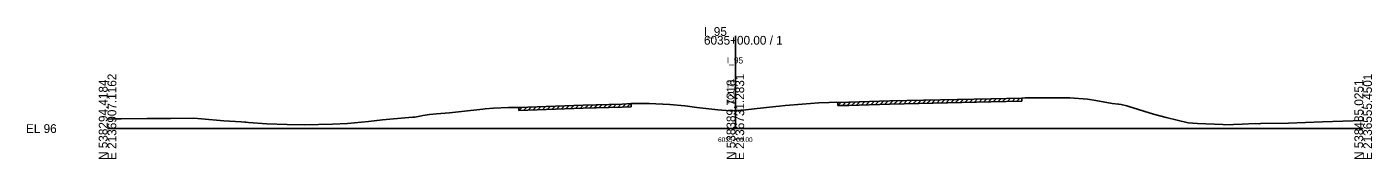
# Model space of a CAD drawing. Extents: x -12534 to 3403, y -1332 to 21983.
# Drawn here: x 1974.3 to 2402.8, y -9.7 to 32.3 of the extents above; entities that cross this region are included whole.
import ezdxf

# ---------------------------------------------------------------- set-up
doc = ezdxf.new("R2010")
doc.units = 0
for name, color, linetype in [('RD_GPK_XS_Cell', 7, 'Continuous'), ('RD_XS_ExGround', 7, 'Continuous'), ('RD_XS_ExPaveRet', 7, 'Continuous'), ('RD_XS_TX_Baseline', 7, 'Continuous'), ('RD_XS_TX_Elev_EX', 7, 'Continuous'), ('RD_XS_TX_Station', 7, 'Continuous')]:
    doc.layers.add(name, color=color, linetype=linetype)

msp = doc.modelspace()

# ---------------------------------------------------------------- linework, layer by layer
at = {"layer": 'RD_GPK_XS_Cell'}
for p, q in [((2200, 0), (2200, 29.49)), ((2000, 0), (2200, 0)), ((2200, 0), (2400, 0))]:
    msp.add_line(p, q, dxfattribs=at)
at = {"layer": 'RD_XS_ExGround'}
msp.add_lwpolyline([(2000, 3.01), (2001.87, 3.08), (2004.3, 3.1), (2012.58, 3.19), (2020.01, 3.26), (2027.52, 3.31), (2029.92, 3.07), (2037.02, 2.5), (2042.56, 2.18), (2043.72, 1.99), (2044.08, 1.99), (2044.85, 1.92), (2050.79, 1.47), (2057.25, 1.27), (2062.7, 1.22), (2071.7, 1.44), (2076.46, 1.67), (2083.08, 2.3), (2087.58, 2.75), (2088.76, 2.87), (2094.71, 3.38), (2097.2, 3.6), (2097.91, 3.68), (2100.02, 4.07), (2100.47, 4.15), (2102.59, 4.44), (2104.8, 4.67), (2108.92, 5.05), (2112.77, 5.42), (2119.55, 6.17), (2120.32, 6.24), (2122.99, 6.45), (2127.72, 6.69), (2129.65, 6.76), (2131.03, 6.75), (2139.76, 7.05), (2151.48, 7.45), (2163.97, 7.8), (2166.85, 7.95), (2172.54, 7.94), (2174.69, 7.9), (2179.16, 7.63), (2183.88, 7.28), (2184.76, 7.11), (2187.68, 6.76), (2194.44, 5.99), (2198.39, 5.66), (2199.18, 5.63), (2200, 5.71), (2203.31, 6.01), (2205.15, 6.18), (2205.99, 6.27), (2212.87, 7.04), (2214.01, 7.16), (2215.88, 7.32), (2221.25, 7.79), (2226.6, 8.16), (2229.87, 8.27), (2232.21, 8.37), (2232.64, 8.34), (2236.19, 8.37), (2249.22, 8.8), (2281.36, 9.51), (2291.23, 9.71), (2292.35, 9.75), (2296.8, 9.82), (2306.58, 9.83), (2312.23, 9.31), (2314.81, 8.89), (2320.05, 7.99), (2322.09, 7.79), (2322.94, 7.64), (2324.72, 7.28), (2325.31, 7.06), (2333.16, 4.64), (2337.25, 3.57), (2344.27, 1.81), (2347.25, 1.58), (2355.34, 1.25), (2355.91, 1.2), (2361.41, 1.41), (2365.57, 1.62), (2366.91, 1.5), (2367.29, 1.61), (2376.22, 1.73), (2387.05, 2.14), (2400, 2.59)], dxfattribs=at)
at = {"layer": 'RD_XS_ExPaveRet'}
for p, q in [((2241.64, 7.55), (2242.68, 8.59)), ((2243.14, 7.6), (2244.18, 8.63)), ((2244.64, 7.65), (2245.68, 8.68)), ((2246.14, 7.7), (2247.18, 8.73)), ((2247.64, 7.75), (2248.68, 8.78)), ((2249.14, 7.79), (2250.17, 8.82)), ((2250.64, 7.83), (2251.66, 8.85)), ((2252.14, 7.86), (2253.16, 8.88)), ((2253.64, 7.9), (2254.66, 8.92)), ((2255.14, 7.93), (2256.16, 8.95)), ((2256.64, 7.96), (2257.66, 8.98)), ((2258.14, 8), (2259.16, 9.02)), ((2259.64, 8.03), (2260.66, 9.05)), ((2261.14, 8.06), (2262.16, 9.08)), ((2262.64, 8.1), (2263.66, 9.12)), ((2264.14, 8.13), (2265.16, 9.15)), ((2265.64, 8.16), (2266.66, 9.18)), ((2267.14, 8.2), (2268.16, 9.22)), ((2268.64, 8.23), (2269.66, 9.25)), ((2270.14, 8.26), (2271.16, 9.28)), ((2271.64, 8.3), (2272.66, 9.32)), ((2273.14, 8.33), (2274.16, 9.35)), ((2274.64, 8.36), (2275.66, 9.38)), ((2276.14, 8.4), (2277.16, 9.42)), ((2277.64, 8.43), (2278.66, 9.45)), ((2279.14, 8.46), (2280.16, 9.48)), ((2280.64, 8.5), (2281.66, 9.52)), ((2281.36, 8.51), (2291.23, 8.71)), ((2282.14, 8.53), (2283.16, 9.55)), ((2283.64, 8.56), (2284.66, 9.58)), ((2285.14, 8.59), (2286.16, 9.61)), ((2286.64, 8.62), (2287.66, 9.64)), ((2288.14, 8.65), (2289.16, 9.67)), ((2289.64, 8.68), (2290.66, 9.7)), ((2291.23, 9.71), (2291.23, 8.71)), ((2131.03, 5.75), (2132.06, 6.78)), ((2131.03, 5.75), (2131.03, 6.75)), ((2131.03, 5.75), (2139.76, 6.05)), ((2132.53, 5.8), (2133.56, 6.83)), ((2134.03, 5.85), (2135.06, 6.89)), ((2135.53, 5.9), (2136.56, 6.94)), ((2137.03, 5.95), (2138.06, 6.99)), ((2138.53, 6), (2139.56, 7.04)), ((2139.76, 6.05), (2151.48, 6.45)), ((2140.03, 6.05), (2141.06, 7.09)), ((2141.53, 6.11), (2142.56, 7.14)), ((2143.03, 6.16), (2144.06, 7.2)), ((2144.53, 6.21), (2145.56, 7.25)), ((2146.03, 6.26), (2147.06, 7.3)), ((2147.53, 6.32), (2148.56, 7.35)), ((2149.03, 6.37), (2150.06, 7.4)), ((2150.53, 6.42), (2151.56, 7.46)), ((2151.48, 6.45), (2163.97, 6.8)), ((2152.03, 6.47), (2153.06, 7.5)), ((2153.53, 6.51), (2154.56, 7.54)), ((2155.03, 6.55), (2156.06, 7.58)), ((2156.53, 6.59), (2157.56, 7.62)), ((2158.03, 6.64), (2159.06, 7.66)), ((2159.53, 6.68), (2160.56, 7.71)), ((2161.03, 6.72), (2162.06, 7.75)), ((2162.53, 6.76), (2163.56, 7.79)), ((2163.97, 6.8), (2166.85, 6.95)), ((2164.03, 6.8), (2165.08, 7.86)), ((2165.53, 6.88), (2166.58, 7.93)), ((2166.85, 7.95), (2166.85, 6.95)), ((2232.64, 7.34), (2233.65, 8.35)), ((2232.64, 7.34), (2232.64, 8.34)), ((2232.64, 7.34), (2236.19, 7.37)), ((2234.14, 7.35), (2235.15, 8.36)), ((2235.64, 7.37), (2236.66, 8.39)), ((2236.19, 7.37), (2249.22, 7.8)), ((2237.14, 7.41), (2238.18, 8.44)), ((2238.64, 7.45), (2239.68, 8.49)), ((2240.14, 7.5), (2241.18, 8.54)), ((2249.22, 7.8), (2281.36, 8.51))]:
    msp.add_line(p, q, dxfattribs=at)

# ---------------------------------------------------------------- texts
at = {"layer": 'RD_GPK_XS_Cell'}
for s, p in [('I_95', (2190, 29.49)), ('6035+00.00 / 1', (2190, 26.69)), ('EL 96', (1974, -1.4))]:
    msp.add_text(s, height=2.8, dxfattribs=at).set_placement(p)
for s, p in [('E 2136907.1162', (2002.8, -10)), ('E 2136731.2831', (2202.8, -10)), ('E 2136555.4501', (2402.8, -10)), ('N 538294.4184', (2000, -10)), ('N 538389.7218', (2200, -10)), ('N 538485.0251', (2400, -10))]:
    msp.add_text(s, height=2.8, rotation=90, dxfattribs=at).set_placement(p)
at = {"layer": 'RD_XS_TX_Baseline'}
msp.add_text('I_95', height=2, dxfattribs=at).set_placement((2197.28, 20.71))
at = {"layer": 'RD_XS_TX_Elev_EX'}
msp.add_text('101.71', height=2, rotation=90, dxfattribs=at).set_placement((2199.5, 7.71))
at = {"layer": 'RD_XS_TX_Station'}
msp.add_text('6035+00.00', height=1.5, dxfattribs=at).set_placement((2194.48, -4.29))

doc.saveas('drawing.dxf')
